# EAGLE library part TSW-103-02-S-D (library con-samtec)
THROUGH-HOLE .025" SQ POST HEADER Source: Samtec TSW.pdf
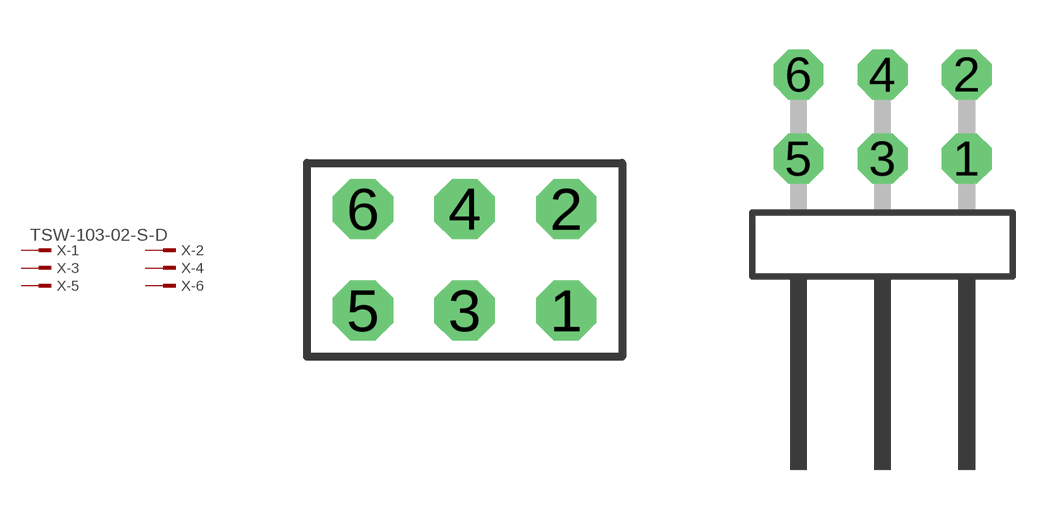
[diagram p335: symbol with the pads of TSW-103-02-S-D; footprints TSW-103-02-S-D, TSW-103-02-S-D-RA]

Designator prefix X; gates -1=MPINV -2=MPIN -3=MPIN -4=MPIN -5=MPIN -6=MPIN

## TSW-103-02-S-D (OC_FARNELL: unknown; OC_NEWARK: unknown)  [TSW-103-02-S-D]
1  -1:1  pas
2  -2:1  pas
3  -3:1  pas
4  -4:1  pas
5  -5:1  pas
6  -6:1  pas

## TSW-103-02-S-D-RA (OC_FARNELL: unknown; OC_NEWARK: unknown)  [TSW-103-02-S-D-RA]
Pads as for TSW-103-02-S-D

## Footprint TSW-103-02-S-D (pad centres in mm)
THROUGH-HOLE .025" SQ POST HEADER Source: Samtec TSW.pdf
drill 1 pad 1.5 octagon: 1 2.54,-1.27; 2 2.54,1.27; 3 0,-1.27; 4 0,1.27; 5 -2.54,-1.27; 6 -2.54,1.27

## Footprint TSW-103-02-S-D-RA (pad centres in mm)
THROUGH-HOLE .025" SQ POST HEADER Source: Samtec TSW.pdf
drill 1 pad 1.5 octagon: 1 2.54,1.524; 2 2.54,4.064; 3 0,1.524; 4 0,4.064; 5 -2.54,1.524; 6 -2.54,4.064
